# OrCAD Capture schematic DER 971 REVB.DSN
size C; title: DER-971; rev: B
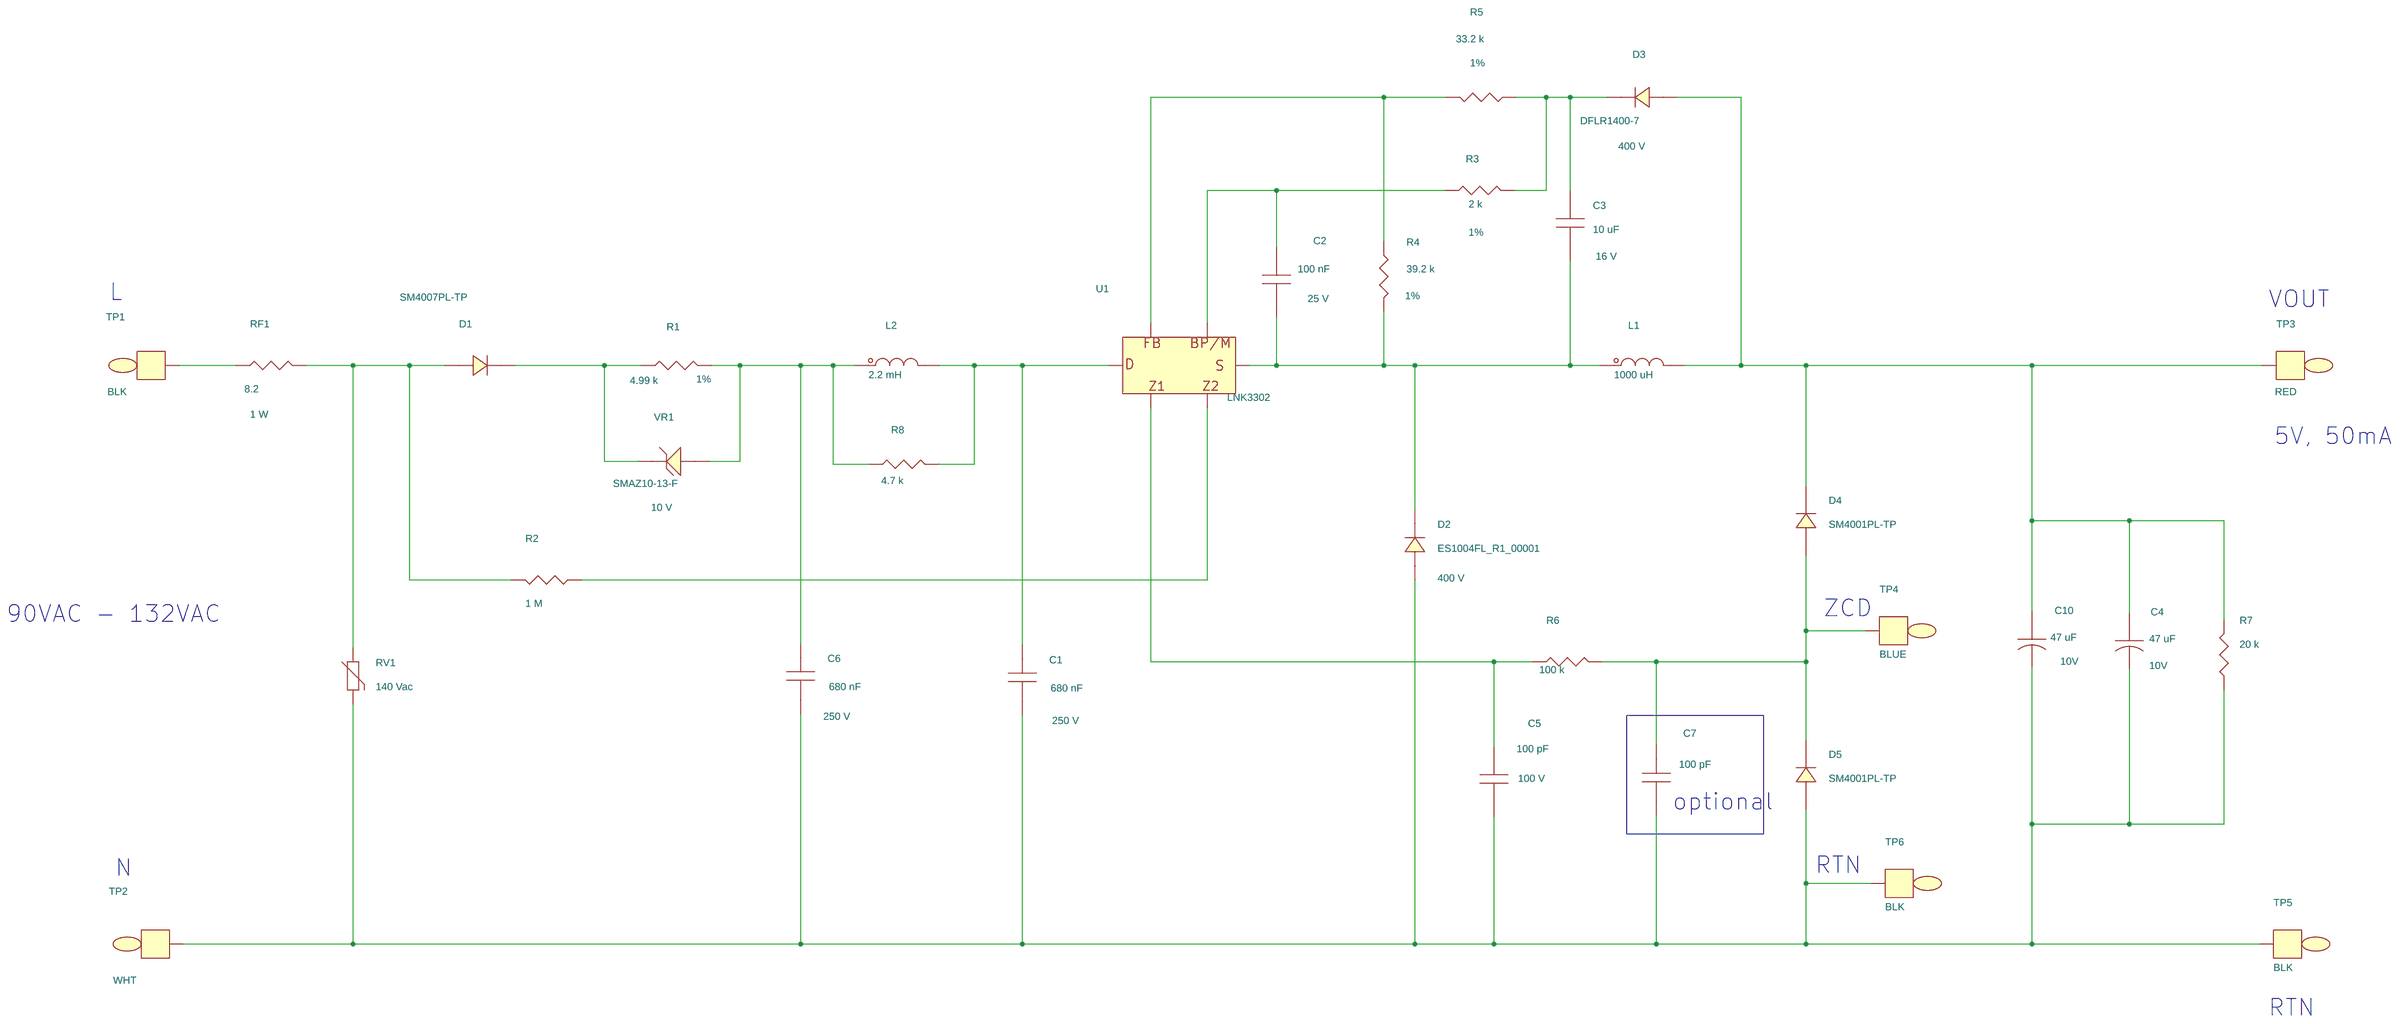
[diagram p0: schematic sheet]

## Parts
C1  680 nF  [pinpcaprad12p3x7p3mm040]
C2  100 nF  [pismc0805]
C3  10 uF  [pismc0805]
C4  47 uF  [pismc1411]
C5  100 pF  [pismc0805]
C6  680 nF  [pinpcaprad12p3x7p3mm040]
C7  100 pF  [pismc0805]
C10  47 uF  [pismc1411]
D1  SM4007PL-TP  [pi_sm_sod-123_12]
D2  ES1004FL_R1_00001  [pi_sm_sod-123_12]
D3  DFLR1400-7  [pismddflr120012]
D4  SM4001PL-TP  [pi_sm_sod-123_12]
D5  SM4001PL-TP  [pi_sm_sod-123_12]
L1  1000 uH  [pi_choke_RLB9012_D2]
L2  2.2 mH  [pi_choke_RL5480-1_d2]
R1  4.99 k  [pismr0805]
R2  1 M  [pismr0805]
R3  2 k  [pismr1206]
R4  39.2 k  [pismr0805]
R5  33.2 k  [pismr0805]
R6  100 k  [pismr0805]
R7  20 k  [pismr0805]
R8  4.7 k  [pismr0805]
RF1  8.2  [pi12wresd180ls575040]
RV1  140 Vac  [pi_np_cap_rad_320x120ls200d040]
TP1  BLK  [pitpkeystone100x100]
TP2  WHT  [pitpkeystone100x100]
TP3  RED  [pitpkeystone100x100]
TP4  BLUE  [pitpkeystone100x100]
TP5  BLK  [pitpkeystone100x100]
TP6  BLK  [pitpkeystone100x100]
U1  LNK3302  [pismso8_nop3]
VR1  SMAZ10-13-F  [pismdo214ac12]

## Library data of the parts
C1 C6 = CAP_NP: Disp_Voltage: 250 V; Part Number: 20-01757-00; Voltage: 250 V
C2 = CAP_NP: Disp_Voltage: 25 V; Part Number: 20-08599-00; Voltage: 25 V
C3 = CAP_NP: Disp_Voltage: 16 V; Part Number: 20-08964-00; Voltage: 16 V
C4 C10 = CAP_POL: Disp_Voltage: 10V; Part Number: 24-00070-00; Voltage: 10 V
C5 C7 = CAP_NP: Disp_Voltage: 100 V; Part Number: 20-00581-00; Voltage: 100 V
D1 = DIODE: Part Number: 15-01070-00
D2 = DIODE: Disp_Voltage: 400 V; Part Number: 15-01796-00
D3 = DIODE: Disp_Voltage: 400 V; Part Number: 15-01310-00
D4 D5 = DIODE: Part Number: 15-01598-00; ROOM: 2
L1 = INDUCTOR_DOT2: Part Number: 30-00363-00
L2 = INDUCTOR_DOT2: Part Number: 30-00272-00
R1 = R: Disp_Tol: 1%; Part Number: 05-03373-00
R2 = R: Part Number: 05-01591-00; ROOM: 1
R3 = R: Disp_Tol: 1%; Part Number: 05-00222-00
R4 = R: Disp_Tol: 1%; Part Number: 05-00741-00; Tol: 1%
R5 = R: Disp_Tol: 1%; Part Number: 05-00734-00
R6 = R: Part Number: 05-01567-00; ROOM: 1
R7 = R: Part Number: 05-01550-00; Tol: 1%
R8 = R: Part Number: 05-01535-00; ROOM: 1
RF1 = RF: ALT_SYMBOLS: pi1wvresd120ls200d040; Disp_Power: 1 W; FPLIST: pi12wresd180ls575040,pi1wvresd120ls200d040; Part Number: 05-06353-00
RV1 = VARISTOR: Part Number: 85-00001-00
TP1 TP5 TP6 = TESTPOINT: Part Number: 35-00079-00
TP2 = TESTPOINT: Part Number: 35-00081-00
TP3 = TESTPOINT: Part Number: 35-00080-00; ROOM: 2
TP4 = TESTPOINT: Part Number: 35-00397-00
U1 = LNK-TNZ: Part Number: 10-01234-00
VR1 = DIODE_ZENER: Disp_Voltage: 10 V; Part Number: 15-01323-00

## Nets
N361822: C1.2 C4.2 C5.2 C6.2 C7.2 C10.2 D2.2 D5.2 R7.2 RV1.2 TP2.1 TP5.1 TP6.1
N595771: D1.2 R2.2 RF1.2 RV1.1
N596154: RF1.1 TP1.1
N596955: C2.1 R3.1 U1.7
N596963: C3.1 D3.1 R3.2 R5.1
N597007: R4.1 R5.2 U1.8
N597039: C4.1 C10.1 D3.2 D4.1 L1.1 R7.1 TP3.1
N597129: C2.2 C3.2 D2.1 L1.2 R4.2 U1.5
N597183: C1.1 L2.1 R8.2 U1.4
N605807: R2.1 U1.2
N607999: C7.1 D4.2 D5.1 R6.2 TP4.1
N609815: C5.1 R6.1 U1.1
N612476: C6.1 L2.2 R1.1 R8.1 VR1.2
N637767: D1.1 R1.2 VR1.1

Not connected (* = marked no-connect by the designer): U1 6

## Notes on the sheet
- L
- VOUT
- 5V, 50mA
- 90VAC - 132VAC
- ZCD
- optional
- N
- RTN
- RTN
